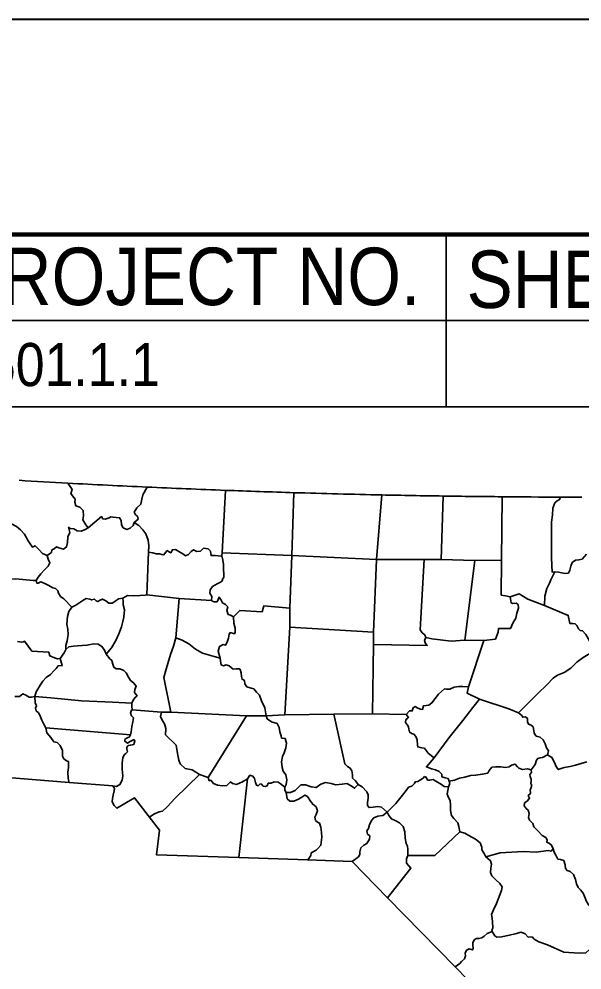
# Model space of a CAD drawing. Extents: x -9.2 to 11.5, y -0.7 to 11.8.
# Drawn here: x 5.741 to 6.721, y 9.345 to 11 of the extents above; entities that cross this region are included whole.
import ezdxf
from ezdxf.enums import TextEntityAlignment as Align

# ---------------------------------------------------------------- set-up
doc = ezdxf.new("R2010")
doc.units = 0
doc.header["$LTSCALE"] = 0.03
doc.layers.add('1', color=7, linetype='Continuous', lineweight=35)
doc.layers.add('63', color=7, linetype='Continuous', lineweight=35)

msp = doc.modelspace()

# ---------------------------------------------------------------- linework, layer by layer
at = {"layer": '1'}
for p, q in [((6.485, 10.625), (6.485, 10.325)), ((4.435, 10.475), (8.135, 10.475))]:
    msp.add_line(p, q, dxfattribs=at)
at = {"layer": '1', "lineweight": 40}
msp.add_lwpolyline([(-8.5, 11), (8.5, 11), (8.5, 0), (-8.5, 0)], close=True, dxfattribs=at)
at = {"layer": '1', "lineweight": 158}
msp.add_lwpolyline([(0.625, 10.625), (8.135, 10.625), (8.135, 0.375), (0.625, 0.375)], close=True, dxfattribs=at)
at = {"layer": '1'}
msp.add_lwpolyline([(4.4355, 10.625), (8.135, 10.625), (8.135, 10.325), (4.4355, 10.325)], close=True, dxfattribs=at)
at = {"layer": '63'}
for p, q in [((6.0951, 10.0707), (6.1006, 10.1796)), ((6.2161, 10.066), (6.22, 10.1755)), ((6.3638, 10.0591), (6.373, 10.1716)), ((6.4762, 10.0593), (6.4795, 10.1696)), ((6.5822, 10.1684), (6.5814, 10.0579)), ((5.9669, 10.0718), (5.964, 9.9975)), ((6.0951, 10.0707), (6.0945, 10.0657)), ((6.2161, 10.066), (6.0951, 10.0707)), ((6.2161, 10.066), (6.213, 9.9746)), ((6.3638, 10.0591), (6.2161, 10.066)), ((6.3638, 10.0591), (6.3585, 9.933)), ((6.4468, 10.059), (6.3638, 10.0591)), ((6.4762, 10.0593), (6.4468, 10.059)), ((6.5349, 10.0576), (6.4762, 10.0593)), ((6.5172, 9.9188), (6.5349, 10.0576)), ((6.5349, 10.0576), (6.5814, 10.0579)), ((5.964, 9.9975), (6.0203, 9.9915)), ((6.0203, 9.9915), (6.0143, 9.9231)), ((6.0203, 9.9915), (6.0766, 9.9881)), ((6.213, 9.9746), (6.2125, 9.9416)), ((6.2125, 9.9416), (6.204, 9.789)), ((6.3585, 9.933), (6.2125, 9.9416)), ((6.3585, 9.933), (6.3583, 9.9113)), ((6.5503, 9.9184), (6.5172, 9.9188)), ((6.5241, 9.8375), (6.5503, 9.9184)), ((6.3568, 9.7908), (6.3583, 9.9113)), ((5.9385, 9.7976), (5.9891, 9.7937)), ((6.0057, 9.7934), (5.9891, 9.7937)), ((6.0057, 9.7934), (6.1372, 9.7873)), ((6.0707, 9.6798), (6.1372, 9.7873)), ((6.1372, 9.7873), (6.1713, 9.7871)), ((6.204, 9.789), (6.1713, 9.7871)), ((6.4156, 9.7893), (6.3568, 9.7908)), ((6.0553, 9.6851), (6.0707, 9.6798)), ((5.9045, 9.6651), (5.8284, 9.6711)), ((6.1393, 9.6775), (6.124, 9.5403))]:
    msp.add_line(p, q, dxfattribs=at)
for points in [[(5.8614, 10.1145), (5.8575, 10.1196), (5.8523, 10.128), (5.8535, 10.1354), (5.8529, 10.1445), (5.8473, 10.1502), (5.8399, 10.1529), (5.8385, 10.1588), (5.8391, 10.1641), (5.8343, 10.1703), (5.8312, 10.174), (5.8337, 10.1808), (5.8312, 10.1845), (5.8263, 10.1922)], [(5.9642, 10.1853), (5.9566, 10.172), (5.9552, 10.164), (5.9535, 10.1556), (5.9461, 10.149), (5.9419, 10.1418), (5.9439, 10.1371), (5.9474, 10.1346), (5.9484, 10.1293), (5.9415, 10.1239)], [(6.6841, 10.1679), (6.6824, 10.1634), (6.6781, 10.1613), (6.674, 10.1576), (6.6707, 10.1488), (6.6703, 10.1371), (6.6685, 10.1243), (6.6681, 10.0619), (6.6693, 10.0373), (6.6741, 10.0379)], [(5.9415, 10.1239), (5.9401, 10.1182), (5.9347, 10.114), (5.9292, 10.1116), (5.9228, 10.1146), (5.9197, 10.1198), (5.9191, 10.1272), (5.9162, 10.1319), (5.9104, 10.1323), (5.9049, 10.1327), (5.901, 10.1337), (5.8979, 10.1318), (5.8915, 10.1292), (5.887, 10.13), (5.8848, 10.1339), (5.8614, 10.1145)], [(5.7185, 10.1261), (5.727, 10.122), (5.7371, 10.1169), (5.7437, 10.1108), (5.7509, 10.1034), (5.7571, 10.0919), (5.7608, 10.0864), (5.7647, 10.0807), (5.7692, 10.0833), (5.7762, 10.0762), (5.782, 10.0696), (5.7904, 10.0663)], [(5.8614, 10.1145), (5.8562, 10.1112), (5.8497, 10.1083), (5.8427, 10.1091), (5.8369, 10.1124), (5.8302, 10.1134), (5.8273, 10.1153), (5.8296, 10.106), (5.8263, 10.0986), (5.8255, 10.0886), (5.8239, 10.081), (5.8185, 10.0775), (5.8105, 10.0795), (5.8064, 10.0812), (5.8023, 10.0777), (5.7984, 10.076), (5.7976, 10.0717), (5.7943, 10.0692), (5.7904, 10.0663)], [(5.9669, 10.0718), (5.9675, 10.0833), (5.966, 10.093), (5.9623, 10.1038), (5.9567, 10.1108), (5.9501, 10.1182), (5.9415, 10.1239)], [(5.7904, 10.0663), (5.7919, 10.0596), (5.7948, 10.0534), (5.7917, 10.0479), (5.7855, 10.0415), (5.7794, 10.0343), (5.7745, 10.0283), (5.7708, 10.0224)], [(5.9669, 10.0718), (5.9741, 10.0708), (5.98, 10.0692), (5.9856, 10.0692), (5.9901, 10.0678), (5.9936, 10.0676), (5.996, 10.0717), (5.9993, 10.0748), (6.003, 10.0721), (6.0055, 10.0711), (6.0082, 10.0762), (6.0137, 10.0764), (6.0195, 10.073), (6.0265, 10.0689), (6.031, 10.0658), (6.0365, 10.0679), (6.041, 10.0734), (6.0451, 10.0763), (6.0507, 10.0732), (6.0575, 10.0739), (6.0626, 10.0788), (6.0704, 10.0776), (6.0745, 10.0735), (6.0756, 10.0661), (6.0827, 10.0661), (6.0877, 10.0659), (6.0932, 10.0653), (6.0945, 10.0657)], [(6.0945, 10.0657), (6.0957, 10.0608), (6.0972, 10.0512), (6.0974, 10.0413), (6.0978, 10.0351), (6.0976, 10.0282), (6.0948, 10.0241), (6.0954, 10.0222), (6.0923, 10.0199), (6.0861, 10.0167), (6.0783, 10.0125), (6.0741, 10.0064), (6.0737, 10.0004), (6.0768, 9.9947), (6.0766, 9.9881)], [(6.6741, 10.0379), (6.6808, 10.0371), (6.6866, 10.0363), (6.6917, 10.0349), (6.6977, 10.0353), (6.7004, 10.0407), (6.7018, 10.0476), (6.7046, 10.054), (6.7104, 10.0583), (6.7161, 10.0588), (6.7217, 10.0596), (6.7293, 10.0686)], [(6.4468, 10.059), (6.4395, 9.9371), (6.4434, 9.9314), (6.4481, 9.9281), (6.4494, 9.9232)], [(6.5967, 9.9945), (6.5883, 9.9959), (6.5809, 9.9973), (6.5814, 10.0579)], [(6.6561, 9.9794), (6.6567, 9.9952), (6.6604, 10.009), (6.6647, 10.0182), (6.6675, 10.024), (6.6741, 10.0379)], [(5.7708, 10.0224), (5.7659, 10.0224), (5.7354, 10.0256), (5.7215, 10.0252), (5.7048, 10.0241)], [(5.7708, 10.0224), (5.7722, 10.0183), (5.7745, 10.0181), (5.779, 10.0206), (5.7823, 10.0191), (5.7874, 10.0167), (5.7932, 10.0138), (5.8002, 10.0101), (5.8049, 10.0087), (5.809, 10.0048), (5.8099, 10.0005), (5.8136, 9.995), (5.8191, 9.9907), (5.8329, 9.9765)], [(6.5967, 9.9945), (6.6121, 9.9992), (6.6269, 9.9904), (6.6561, 9.9794)], [(5.8329, 9.9765), (5.8403, 9.9796), (5.8471, 9.9844), (5.8541, 9.9891), (5.8584, 9.9911), (5.8643, 9.9903), (5.8676, 9.9889), (5.8726, 9.9904), (5.8754, 9.9875), (5.8785, 9.9859), (5.8828, 9.9887), (5.8865, 9.9904), (5.8923, 9.9875), (5.8976, 9.9834), (5.9036, 9.9832), (5.9083, 9.9863), (5.9143, 9.9908), (5.9221, 9.9917)], [(5.8929, 9.8945), (5.9025, 9.9056), (5.9099, 9.918), (5.9152, 9.9301), (5.9195, 9.9418), (5.9222, 9.9515), (5.9236, 9.9589), (5.9246, 9.9718), (5.9227, 9.9804), (5.9225, 9.9859), (5.9221, 9.9917)], [(5.9221, 9.9917), (5.9303, 9.9964), (5.9403, 9.9962), (5.952, 9.9967), (5.9607, 9.9973), (5.964, 9.9975)], [(6.0766, 9.9881), (6.0782, 9.9867), (6.0811, 9.9854), (6.0862, 9.9854), (6.0897, 9.9939), (6.0932, 9.9883), (6.0953, 9.9836), (6.1008, 9.981), (6.1047, 9.9769), (6.1033, 9.9705), (6.1056, 9.9635), (6.1097, 9.9623), (6.1146, 9.9592)], [(6.5503, 9.9184), (6.5708, 9.9207), (6.5753, 9.9329), (6.5763, 9.9394), (6.5841, 9.939), (6.5968, 9.9393), (6.6015, 9.9495), (6.606, 9.9573), (6.6079, 9.9658), (6.6109, 9.9746), (6.6101, 9.9808), (6.6068, 9.9832), (6.6006, 9.9826), (6.5984, 9.9838), (6.5967, 9.9945)], [(5.8329, 9.9765), (5.8278, 9.9685), (5.8258, 9.9599), (5.8246, 9.9465), (5.826, 9.9377), (5.8267, 9.9287), (5.8265, 9.925), (5.8253, 9.9176), (5.8228, 9.9096), (5.8226, 9.9024)], [(6.1146, 9.9592), (6.1257, 9.9705), (6.1643, 9.9684), (6.1676, 9.9786), (6.213, 9.9746)], [(6.6561, 9.9794), (6.6975, 9.962), (6.7004, 9.9477), (6.7055, 9.9479), (6.7098, 9.9471), (6.7127, 9.9444), (6.7152, 9.9387), (6.7181, 9.9358), (6.7224, 9.9352), (6.7283, 9.9289), (6.7323, 9.9215), (6.744, 9.901)], [(6.1146, 9.9592), (6.1153, 9.9486), (6.1174, 9.9395), (6.1176, 9.9328), (6.1163, 9.9299), (6.1089, 9.9321), (6.1073, 9.929), (6.1057, 9.9221), (6.1034, 9.9153), (6.1006, 9.9101), (6.0967, 9.911), (6.0905, 9.9079), (6.0879, 9.8994), (6.0916, 9.8873)], [(5.7341, 9.8206), (5.7423, 9.821), (5.7478, 9.8253), (5.753, 9.8229), (5.7587, 9.8198), (5.7626, 9.8196), (5.7688, 9.8209), (5.771, 9.8287), (5.7737, 9.8338), (5.778, 9.8406), (5.7827, 9.8472), (5.7886, 9.8538), (5.7962, 9.8591), (5.8024, 9.8661), (5.8061, 9.8694), (5.8093, 9.8741), (5.8165, 9.8745), (5.813, 9.8868), (5.8083, 9.8866), (5.8029, 9.8881), (5.7949, 9.8915), (5.7931, 9.8977), (5.7637, 9.8995), (5.7509, 9.9169), (5.749, 9.9161), (5.7456, 9.9152), (5.7386, 9.9167)], [(6.0143, 9.9231), (6.01, 9.9081), (6.0051, 9.8937), (6.0004, 9.8785), (5.9963, 9.8642), (5.9933, 9.8539), (6.0057, 9.7934)], [(6.0916, 9.8873), (6.0809, 9.8906), (6.0608, 9.8961), (6.0486, 9.9031), (6.0371, 9.9123), (6.0252, 9.919), (6.0143, 9.9231)], [(6.4494, 9.9232), (6.4475, 9.9182), (6.4492, 9.9131), (6.4519, 9.9098), (6.3583, 9.9113)], [(6.4494, 9.9232), (6.4601, 9.9211), (6.4936, 9.9171), (6.5172, 9.9188)], [(5.8929, 9.8945), (5.89, 9.9013), (5.8857, 9.9079), (5.8791, 9.9116), (5.8713, 9.9122), (5.8594, 9.9101), (5.8432, 9.9088), (5.8358, 9.9082), (5.8282, 9.9071), (5.8226, 9.9024), (5.82, 9.8969), (5.813, 9.8868)], [(6.744, 9.901), (6.7237, 9.8886), (6.7126, 9.8804), (6.7018, 9.8703), (6.6907, 9.8623), (6.679, 9.8579), (6.6714, 9.8524), (6.6606, 9.8415), (6.6442, 9.8254), (6.6111, 9.7925)], [(5.9385, 9.7976), (5.9379, 9.8041), (5.9379, 9.809), (5.9399, 9.8146), (5.9426, 9.8187), (5.9469, 9.8222), (5.9422, 9.8277), (5.9426, 9.8327), (5.9452, 9.8386), (5.9407, 9.8446), (5.9353, 9.8486), (5.9316, 9.8546), (5.9275, 9.8618), (5.924, 9.8661), (5.917, 9.8691), (5.9104, 9.8687), (5.9061, 9.8716), (5.9047, 9.8771), (5.9026, 9.8833), (5.8993, 9.8865), (5.8929, 9.8945)], [(6.1713, 9.7871), (6.169, 9.8009), (6.1635, 9.8132), (6.1597, 9.823), (6.1546, 9.8286), (6.1501, 9.8341), (6.1453, 9.8351), (6.1379, 9.8376), (6.1346, 9.8431), (6.1336, 9.8488), (6.1307, 9.8503), (6.1297, 9.8509), (6.1284, 9.8556), (6.1278, 9.8618), (6.1261, 9.8679), (6.1243, 9.8691), (6.1192, 9.8687), (6.114, 9.8683), (6.107, 9.8742), (6.1021, 9.8757), (6.0974, 9.874), (6.093, 9.8761), (6.0922, 9.882), (6.0916, 9.8873)], [(6.4156, 9.7893), (6.4211, 9.7958), (6.4258, 9.7958), (6.4273, 9.8012), (6.4308, 9.8031), (6.4359, 9.8004), (6.4402, 9.7986), (6.4437, 9.7981), (6.4455, 9.8045), (6.4546, 9.8056), (6.4603, 9.8095), (6.4658, 9.8171), (6.4718, 9.8251), (6.4771, 9.8296), (6.4818, 9.8341), (6.4853, 9.8337), (6.4911, 9.8333), (6.4991, 9.8373), (6.5071, 9.8379), (6.5141, 9.8379), (6.5241, 9.8375)], [(6.5433, 9.8164), (6.5213, 9.8266), (6.5241, 9.8375)], [(5.788, 9.7662), (5.7849, 9.7712), (5.781, 9.7794), (5.7775, 9.788), (5.775, 9.7923), (5.7711, 9.7958), (5.7697, 9.8005), (5.7715, 9.8048), (5.7696, 9.8099), (5.7688, 9.8208)], [(5.7688, 9.8208), (5.7965, 9.8182), (5.85, 9.813), (5.9038, 9.8108), (5.9379, 9.809)], [(6.5433, 9.8164), (6.5314, 9.8016), (6.5142, 9.779), (6.4903, 9.7494), (6.4638, 9.7142)], [(6.6111, 9.7925), (6.5943, 9.7991), (6.5433, 9.8164)], [(5.9354, 9.7538), (5.9366, 9.7592), (5.9378, 9.7686), (5.9394, 9.7766), (5.9404, 9.7834), (5.9373, 9.7871), (5.9355, 9.7918), (5.9373, 9.7967), (5.9385, 9.7976)], [(5.9891, 9.7937), (5.9875, 9.7861), (5.9906, 9.7796), (5.9947, 9.773), (5.9968, 9.7648), (5.996, 9.7541), (6.0147, 9.7361), (6.0174, 9.7218), (6.0193, 9.7101), (6.0216, 9.7033), (6.0308, 9.6953), (6.0425, 9.6929), (6.0553, 9.6851)], [(6.1713, 9.7871), (6.1734, 9.782), (6.181, 9.7765), (6.1907, 9.7736), (6.1944, 9.7671), (6.1956, 9.7595), (6.1975, 9.7525), (6.1985, 9.7484), (6.2047, 9.7476), (6.2068, 9.7396), (6.2058, 9.7312), (6.2027, 9.7225), (6.1998, 9.7162), (6.1984, 9.7069), (6.1993, 9.6973), (6.2009, 9.6909), (6.2057, 9.6842), (6.2075, 9.676), (6.2065, 9.6677), (6.2043, 9.663), (6.2043, 9.6634), (6.2041, 9.6579), (6.2061, 9.6538)], [(6.204, 9.789), (6.2892, 9.7902), (6.3568, 9.7908)], [(6.3316, 9.6676), (6.3273, 9.6739), (6.322, 9.6789), (6.3217, 9.6844), (6.3209, 9.6916), (6.318, 9.6961), (6.3129, 9.6992), (6.3085, 9.7035), (6.2892, 9.7902)], [(6.4638, 9.7142), (6.4593, 9.7175), (6.4535, 9.7224), (6.4504, 9.7265), (6.4472, 9.7308), (6.4428, 9.7314), (6.44, 9.7318), (6.4356, 9.7329), (6.435, 9.7363), (6.4344, 9.7456), (6.4319, 9.7509), (6.4288, 9.755), (6.4249, 9.7564), (6.4214, 9.7591), (6.42, 9.7638), (6.4193, 9.7679), (6.4175, 9.771), (6.4142, 9.7757), (6.415, 9.7806), (6.4177, 9.7825), (6.4195, 9.7843), (6.4156, 9.7893)], [(6.6111, 9.7925), (6.6169, 9.7876), (6.6182, 9.7847), (6.6231, 9.7854), (6.6264, 9.7827), (6.6268, 9.7766), (6.6285, 9.7725), (6.6328, 9.7708), (6.6367, 9.7679), (6.6377, 9.7616), (6.6381, 9.7569), (6.6419, 9.752), (6.6484, 9.7497), (6.654, 9.7456), (6.6571, 9.7384), (6.6598, 9.7313), (6.6631, 9.7263), (6.6612, 9.7194)], [(6.6296, 9.2182), (6.5007, 9.3501), (6.383, 9.4706), (6.3213, 9.5338), (6.2434, 9.5365), (6.124, 9.5405), (5.9804, 9.5454), (5.9861, 9.5883), (5.9424, 9.6443), (5.9116, 9.6264), (5.9067, 9.6311), (5.9036, 9.6376), (5.9038, 9.6432), (5.905, 9.6491), (5.9066, 9.6565), (5.9072, 9.6608), (5.9045, 9.6651), (5.9111, 9.6639), (5.9169, 9.6674), (5.921, 9.6754), (5.9218, 9.6828), (5.9209, 9.6943), (5.9209, 9.7054), (5.9219, 9.714), (5.9243, 9.7192), (5.9274, 9.7214), (5.9299, 9.7245), (5.929, 9.729), (5.9292, 9.7325), (5.9313, 9.7354), (5.9352, 9.7362), (5.9385, 9.7368), (5.9409, 9.7373), (5.943, 9.7436), (5.9411, 9.7459), (5.9368, 9.7436), (5.9346, 9.7424), (5.9302, 9.7397), (5.9255, 9.7428), (5.9257, 9.7457), (5.9284, 9.7483), (5.9329, 9.7498), (5.9354, 9.7539), (5.788, 9.7663), (5.7895, 9.7573), (5.7967, 9.7493), (5.8016, 9.7421), (5.8076, 9.7407), (5.8127, 9.7352), (5.8167, 9.7268), (5.8169, 9.7167), (5.819, 9.7124), (5.8239, 9.7089), (5.8276, 9.7075), (5.8276, 9.6974), (5.8264, 9.689), (5.8266, 9.6783), (5.8284, 9.6712), (5.6921, 9.682)], [(6.6612, 9.7194), (6.6526, 9.7146), (6.6489, 9.714), (6.6446, 9.7127), (6.6422, 9.7099), (6.6397, 9.7027), (6.6332, 9.693)], [(6.6612, 9.7194), (6.6691, 9.7146), (6.673, 9.7069), (6.6763, 9.6989), (6.68, 9.6937), (6.6903, 9.6972), (6.7007, 9.6989), (6.7104, 9.701), (6.7299, 9.7072)], [(6.4904, 9.6736), (6.4882, 9.678), (6.4832, 9.6794), (6.4775, 9.6812), (6.4772, 9.6853), (6.4729, 9.6902), (6.4665, 9.6931), (6.4596, 9.6949), (6.4505, 9.6982), (6.4638, 9.7142)], [(6.6332, 9.693), (6.6266, 9.6949), (6.6178, 9.6936), (6.6114, 9.6961), (6.6089, 9.6983), (6.6054, 9.7028), (6.599, 9.7012), (6.5945, 9.6985), (6.5882, 9.697), (6.5799, 9.6983), (6.5717, 9.6984), (6.5645, 9.6978), (6.5598, 9.6921), (6.5574, 9.6871), (6.5479, 9.6855), (6.5366, 9.684), (6.5272, 9.6832), (6.5173, 9.6803), (6.5081, 9.6788), (6.4993, 9.6751), (6.4904, 9.6736)], [(5.9688, 9.6112), (5.977, 9.6168), (5.9854, 9.6201), (5.9913, 9.6213), (5.9993, 9.6289), (6.0133, 9.6438), (6.0553, 9.6851)], [(6.2043, 9.663), (6.196, 9.6692), (6.1925, 9.6716), (6.1856, 9.6722), (6.18, 9.6702), (6.1751, 9.6697), (6.1731, 9.665), (6.1706, 9.6644), (6.1665, 9.6648), (6.1628, 9.6685), (6.1607, 9.6683), (6.1574, 9.6654), (6.1546, 9.6664), (6.1527, 9.6713), (6.1512, 9.6783), (6.1481, 9.6822), (6.1434, 9.6836), (6.1393, 9.6775)], [(6.6332, 9.693), (6.6336, 9.6887), (6.6307, 9.685), (6.6315, 9.6817), (6.633, 9.677), (6.633, 9.6737), (6.6326, 9.6686), (6.6338, 9.668), (6.6338, 9.6641), (6.631, 9.6575), (6.632, 9.6534), (6.6318, 9.6532), (6.631, 9.6511), (6.6279, 9.6485), (6.6302, 9.6438), (6.6261, 9.6388), (6.6212, 9.6355), (6.6206, 9.6306), (6.6241, 9.6259), (6.6278, 9.6228), (6.6294, 9.6169), (6.6282, 9.6103), (6.6303, 9.6058), (6.6356, 9.5998), (6.6379, 9.5939), (6.6447, 9.5871), (6.6523, 9.5791), (6.6583, 9.5755), (6.6608, 9.5714), (6.66, 9.5674), (6.6651, 9.565), (6.6686, 9.5621), (6.6715, 9.5558)], [(6.1393, 9.6775), (6.1289, 9.6717), (6.1264, 9.6703), (6.12, 9.6678), (6.113, 9.6694), (6.1095, 9.6721), (6.1032, 9.6661), (6.0956, 9.6653), (6.0866, 9.6663), (6.0796, 9.6695), (6.0754, 9.6749), (6.0724, 9.6742), (6.0707, 9.6798)], [(6.2061, 9.6538), (6.214, 9.6536), (6.2222, 9.6571), (6.2265, 9.6618), (6.232, 9.6672), (6.2402, 9.667), (6.2497, 9.6637), (6.2585, 9.6621), (6.2667, 9.6679), (6.2749, 9.6708), (6.285, 9.6691), (6.293, 9.6671), (6.3037, 9.6679), (6.3123, 9.6692), (6.3193, 9.6653), (6.3255, 9.6612), (6.3316, 9.6676)], [(6.3316, 9.6676), (6.3388, 9.6635), (6.3469, 9.6551), (6.3493, 9.6496), (6.3494, 9.643), (6.3479, 9.6368), (6.348, 9.6313), (6.3508, 9.6274), (6.358, 9.6282), (6.366, 9.6293), (6.3726, 9.6281), (6.3823, 9.6195)], [(6.489, 9.6636), (6.4816, 9.6644), (6.4767, 9.6677), (6.467, 9.6732), (6.4623, 9.6763), (6.4565, 9.675), (6.4526, 9.6752), (6.4501, 9.6801), (6.4475, 9.6814), (6.4448, 9.6785), (6.4354, 9.6731), (6.4311, 9.6723), (6.4296, 9.6692), (6.4251, 9.6647), (6.4196, 9.6632), (6.4155, 9.6571), (6.4089, 9.6489), (6.3973, 9.6345), (6.3893, 9.6262), (6.3823, 9.6195)], [(6.489, 9.6636), (6.4911, 9.6693), (6.4904, 9.6736)], [(6.2434, 9.5356), (6.2491, 9.5439), (6.2499, 9.5486), (6.2584, 9.5535), (6.2614, 9.5562), (6.267, 9.5619), (6.2684, 9.5761), (6.2679, 9.5839), (6.2665, 9.5931), (6.2642, 9.6003), (6.2611, 9.6018), (6.2576, 9.6052), (6.2562, 9.6108), (6.2586, 9.6153), (6.2609, 9.6219), (6.2584, 9.6286), (6.2528, 9.6331), (6.2485, 9.6383), (6.2436, 9.6465), (6.239, 9.6491), (6.2337, 9.6454), (6.228, 9.6423), (6.2199, 9.6386), (6.213, 9.6384), (6.2084, 9.6429), (6.2061, 9.6538)], [(6.5085, 9.5854), (6.507, 9.5947), (6.505, 9.6008), (6.4986, 9.6082), (6.4941, 9.6139), (6.4926, 9.6221), (6.4926, 9.632), (6.4921, 9.6396), (6.4891, 9.6449), (6.487, 9.6509), (6.489, 9.6636)], [(6.3823, 9.6195), (6.3749, 9.6135), (6.3659, 9.6126), (6.3589, 9.6097), (6.3548, 9.6048), (6.3517, 9.5972), (6.3495, 9.5911), (6.347, 9.5867), (6.3481, 9.5812), (6.3522, 9.5781), (6.3512, 9.5722), (6.3471, 9.565), (6.3415, 9.5619), (6.3364, 9.5576), (6.3344, 9.5504), (6.3346, 9.5455), (6.3325, 9.5418), (6.3213, 9.5337)], [(6.3823, 9.6195), (6.3854, 9.6135), (6.3895, 9.6076), (6.3973, 9.6041), (6.4035, 9.6006), (6.4103, 9.5945), (6.4128, 9.585), (6.4134, 9.5744), (6.4155, 9.5651), (6.4176, 9.56), (6.4182, 9.5547), (6.418, 9.5442)], [(6.5085, 9.5854), (6.4653, 9.5441), (6.418, 9.5442)], [(6.554, 9.5416), (6.5509, 9.5473), (6.5468, 9.5539), (6.5468, 9.5588), (6.5443, 9.5658), (6.5363, 9.5727), (6.5247, 9.5791), (6.5176, 9.5826), (6.5085, 9.5854)], [(6.554, 9.5416), (6.5788, 9.5488), (6.6189, 9.551), (6.6415, 9.5496), (6.6625, 9.5525), (6.6678, 9.5515), (6.6715, 9.5558)], [(6.6715, 9.5558), (6.6733, 9.5498), (6.6762, 9.5447), (6.6797, 9.5379), (6.6843, 9.5371), (6.6898, 9.5353), (6.6919, 9.5275), (6.6927, 9.5211), (6.6954, 9.5177), (6.701, 9.5164), (6.7065, 9.5111), (6.71, 9.5021), (6.7119, 9.4949), (6.7148, 9.4885), (6.7191, 9.484), (6.7236, 9.4783), (6.7263, 9.4717), (6.7294, 9.4641), (6.7331, 9.4578), (6.7399, 9.4512), (6.7455, 9.4402)], [(6.418, 9.5442), (6.4158, 9.5382), (6.416, 9.5308), (6.4236, 9.5222), (6.383, 9.4706)], [(6.565, 9.4119), (6.5642, 9.4135), (6.5662, 9.4182), (6.5656, 9.4285), (6.5649, 9.4351), (6.5641, 9.4416), (6.5674, 9.4494), (6.5727, 9.4605), (6.5786, 9.4755), (6.5813, 9.4831), (6.5825, 9.4895), (6.5786, 9.4955), (6.5712, 9.5014), (6.5644, 9.5084), (6.5621, 9.5143), (6.5625, 9.5217), (6.5637, 9.5289), (6.5624, 9.5348), (6.554, 9.5416)], [(6.565, 9.4119), (6.5566, 9.408), (6.551, 9.4034), (6.5469, 9.4006), (6.542, 9.3995), (6.5377, 9.3997), (6.5338, 9.3972), (6.5313, 9.3921), (6.5314, 9.3888), (6.5318, 9.3821), (6.531, 9.3798), (6.525, 9.3818), (6.5205, 9.3792), (6.5178, 9.3738), (6.5187, 9.3693), (6.517, 9.364), (6.5117, 9.3596), (6.5086, 9.3561), (6.5007, 9.3501)], [(6.7446, 9.3833), (6.7348, 9.3802), (6.7282, 9.3747), (6.7163, 9.374), (6.69, 9.3758), (6.6614, 9.3885), (6.6462, 9.3936), (6.6384, 9.3983), (6.6345, 9.4022), (6.6277, 9.4019), (6.6223, 9.4075), (6.6155, 9.4105), (6.6051, 9.4079), (6.5952, 9.4052), (6.5814, 9.4025), (6.573, 9.4016), (6.5695, 9.4041), (6.565, 9.4119)]]:
    msp.add_lwpolyline(points, dxfattribs=at)
for centre, radius, start, end in [((6.724, 26.7424), 16.5745, 266.60071, 266.89521), ((6.7237, 26.7373), 16.5695, 266.89528, 267.3729), ((6.7237, 26.737), 16.5691, 267.37283, 267.84495), ((6.7238, 26.7399), 16.572, 267.84496, 268.25795), ((6.7238, 26.7394), 16.5715, 268.25789, 268.78707), ((6.7238, 26.7415), 16.5736, 268.78705, 269.15534), ((6.7238, 26.7437), 16.5758, 269.15557, 269.51035), ((6.7238, 26.7355), 16.5677, 269.51025, 269.86274), ((6.7237, 26.7426), 16.5748, 269.86288, 269.99214)]:
    msp.add_arc(centre, radius, start, end, dxfattribs=at)

# ---------------------------------------------------------------- texts
at = {"layer": '1', "width": 0.9}
for s, height, p in [('STATE PROJECT NO.', 0.1, (5.8246, 10.502)), ('SHEET NO.', 0.1, (6.8449, 10.497)), ('34501.1.1', 0.075, (5.7857, 10.361))]:
    msp.add_text(s, height=height, dxfattribs=at).set_placement(p, align=Align.CENTER)

doc.saveas('drawing.dxf')
